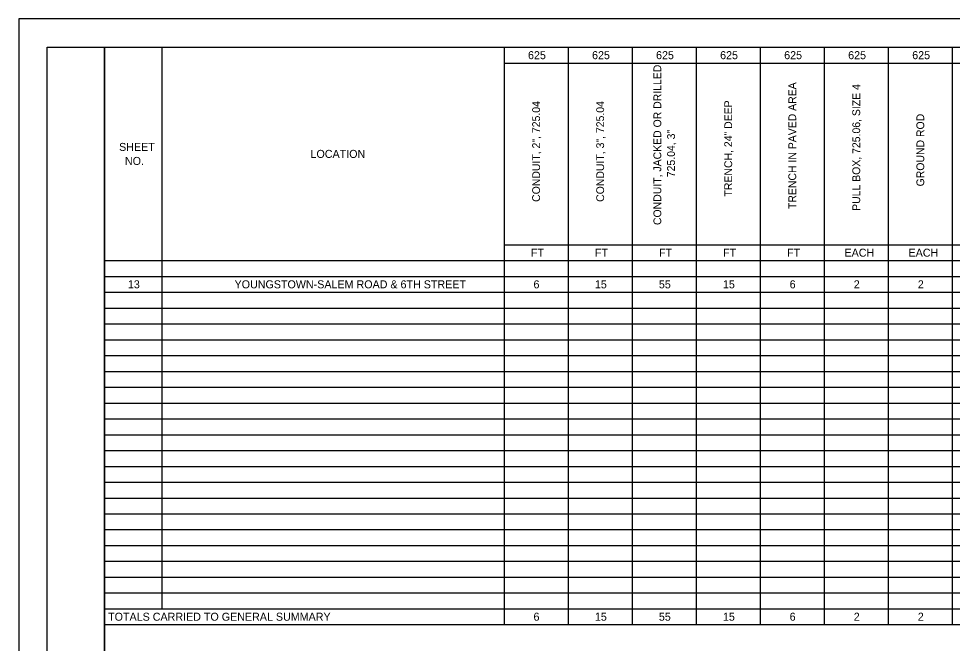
# Model space of a CAD drawing. Extents: x 0 to 34, y 0 to 22.
# Drawn here: x 0 to 16.33, y 11.08 to 22 of the extents above; entities that cross this region are included whole.
import ezdxf

# ---------------------------------------------------------------- set-up
doc = ezdxf.new("R2010")
doc.units = 0
for name, color, linetype in [('SH_Border', 7, 'Continuous'), ('SH_Cut_Line', 7, 'Continuous'), ('SH_Data', 7, 'Continuous')]:
    doc.layers.add(name, color=color, linetype=linetype)

msp = doc.modelspace()

# ---------------------------------------------------------------- linework, layer by layer
at = {"layer": 'SH_Border'}
for points in [[(0.5, 21.5), (1.5, 21.5), (1.5, 0.5), (0.5, 0.5)], [(1.5, 21.5), (33.5, 21.5), (33.5, 0.5), (1.5, 0.5)]]:
    msp.add_lwpolyline(points, close=True, dxfattribs=at)
at = {"layer": 'SH_Cut_Line'}
msp.add_lwpolyline([(0, 0), (34, 0), (34, 22), (0, 22)], close=True, dxfattribs=at)
at = {"layer": 'SH_Data'}
for p, q in [((1.5, 21.5), (6.249, 21.5)), ((1.5, 21.5), (1.5, 21.223)), ((2.504, 21.5), (2.504, 21.223)), ((6.249, 21.5), (7.716, 21.5)), ((7.716, 21.5), (14.086, 21.5)), ((8.488, 21.5), (8.488, 21.223)), ((9.608, 21.5), (9.608, 21.223)), ((10.727, 21.5), (10.727, 21.223)), ((11.847, 21.5), (11.847, 21.223)), ((12.966, 21.5), (12.966, 21.223)), ((14.086, 21.5), (15.206, 21.5)), ((14.086, 21.5), (14.086, 21.223)), ((15.206, 21.5), (16.325, 21.5)), ((15.206, 21.5), (15.206, 21.223)), ((16.325, 21.5), (23.043, 21.5)), ((16.325, 21.5), (16.325, 21.223)), ((1.5, 21.223), (1.5, 20.947)), ((2.504, 21.223), (2.504, 20.947)), ((8.488, 21.223), (14.086, 21.223)), ((8.488, 21.223), (8.488, 20.947)), ((9.608, 21.223), (9.608, 20.947)), ((10.727, 21.223), (10.727, 20.947)), ((11.847, 21.223), (11.847, 20.947)), ((12.966, 21.223), (12.966, 20.947)), ((14.086, 21.223), (15.206, 21.223)), ((14.086, 21.223), (14.086, 20.947)), ((15.206, 21.223), (16.325, 21.223)), ((15.206, 21.223), (15.206, 20.947)), ((16.325, 21.223), (23.043, 21.223)), ((16.325, 21.223), (16.325, 20.947)), ((1.5, 20.947), (1.5, 20.67)), ((2.504, 20.947), (2.504, 20.67)), ((8.488, 20.947), (8.488, 20.67)), ((9.608, 20.947), (9.608, 20.67)), ((10.727, 20.947), (10.727, 20.67)), ((11.847, 20.947), (11.847, 20.67)), ((12.966, 20.947), (12.966, 20.67)), ((14.086, 20.947), (14.086, 20.67)), ((15.206, 20.947), (15.206, 20.67)), ((16.325, 20.947), (16.325, 20.67)), ((1.5, 20.67), (1.5, 20.393)), ((2.504, 20.67), (2.504, 20.393)), ((8.488, 20.67), (8.488, 20.393)), ((9.608, 20.67), (9.608, 20.393)), ((10.727, 20.67), (10.727, 20.393)), ((11.847, 20.67), (11.847, 20.393)), ((12.966, 20.67), (12.966, 20.393)), ((14.086, 20.67), (14.086, 20.393)), ((15.206, 20.67), (15.206, 20.393)), ((16.325, 20.67), (16.325, 20.393)), ((1.5, 20.393), (1.5, 20.116)), ((2.504, 20.393), (2.504, 20.116)), ((8.488, 20.393), (8.488, 20.116)), ((9.608, 20.393), (9.608, 20.116)), ((10.727, 20.393), (10.727, 20.116)), ((11.847, 20.393), (11.847, 20.116)), ((12.966, 20.393), (12.966, 20.116)), ((14.086, 20.393), (14.086, 20.116)), ((15.206, 20.393), (15.206, 20.116)), ((16.325, 20.393), (16.325, 20.116)), ((1.5, 20.116), (1.5, 19.84)), ((2.504, 20.116), (2.504, 19.84)), ((8.488, 20.116), (8.488, 19.84)), ((9.608, 20.116), (9.608, 19.84)), ((10.727, 20.116), (10.727, 19.84)), ((11.847, 20.116), (11.847, 19.84)), ((12.966, 20.116), (12.966, 19.84)), ((14.086, 20.116), (14.086, 19.84)), ((15.206, 20.116), (15.206, 19.84)), ((16.325, 20.116), (16.325, 19.84)), ((1.5, 19.84), (1.5, 19.563)), ((2.504, 19.84), (2.504, 19.563)), ((8.488, 19.84), (8.488, 19.563)), ((9.608, 19.84), (9.608, 19.563)), ((10.727, 19.84), (10.727, 19.563)), ((11.847, 19.84), (11.847, 19.563)), ((12.966, 19.84), (12.966, 19.563)), ((14.086, 19.84), (14.086, 19.563)), ((15.206, 19.84), (15.206, 19.563)), ((16.325, 19.84), (16.325, 19.563)), ((1.5, 19.563), (1.5, 18.878)), ((2.504, 19.563), (2.504, 18.878)), ((8.488, 19.563), (8.488, 18.878)), ((9.608, 19.563), (9.608, 18.878)), ((10.727, 19.563), (10.727, 18.878)), ((11.847, 19.563), (11.847, 18.878)), ((12.966, 19.563), (12.966, 18.878)), ((14.086, 19.563), (14.086, 18.878)), ((15.206, 19.563), (15.206, 18.878)), ((16.325, 19.563), (16.325, 18.878)), ((1.5, 18.878), (1.5, 18.048)), ((2.504, 18.878), (2.504, 18.048)), ((8.488, 18.878), (8.488, 18.048)), ((9.608, 18.878), (9.608, 18.048)), ((10.727, 18.878), (10.727, 18.048)), ((11.847, 18.878), (11.847, 18.048)), ((12.966, 18.878), (12.966, 18.048)), ((14.086, 18.878), (14.086, 18.048)), ((15.206, 18.878), (15.206, 18.048)), ((16.325, 18.878), (16.325, 18.048)), ((1.5, 18.048), (1.5, 17.771)), ((2.504, 18.048), (2.504, 17.771)), ((8.488, 18.048), (14.086, 18.048)), ((8.488, 18.048), (8.488, 17.771)), ((9.608, 18.048), (9.608, 17.771)), ((10.727, 18.048), (10.727, 17.771)), ((11.847, 18.048), (11.847, 17.771)), ((12.966, 18.048), (12.966, 17.771)), ((14.086, 18.048), (15.206, 18.048)), ((14.086, 18.048), (14.086, 17.771)), ((15.206, 18.048), (16.325, 18.048)), ((15.206, 18.048), (15.206, 17.771)), ((16.325, 18.048), (23.043, 18.048)), ((16.325, 18.048), (16.325, 17.771)), ((1.5, 17.771), (6.249, 17.771)), ((1.5, 17.771), (1.5, 17.218)), ((2.504, 17.771), (2.504, 17.218)), ((6.249, 17.771), (7.716, 17.771)), ((7.716, 17.771), (14.086, 17.771)), ((8.488, 17.771), (8.488, 17.218)), ((9.608, 17.771), (9.608, 17.218)), ((10.727, 17.771), (10.727, 17.218)), ((11.847, 17.771), (11.847, 17.218)), ((12.966, 17.771), (12.966, 17.218)), ((14.086, 17.771), (15.206, 17.771)), ((14.086, 17.771), (14.086, 17.218)), ((15.206, 17.771), (16.325, 17.771)), ((15.206, 17.771), (15.206, 17.218)), ((16.325, 17.771), (23.043, 17.771)), ((16.325, 17.771), (16.325, 17.218)), ((1.5, 17.494), (6.249, 17.494)), ((6.249, 17.494), (7.716, 17.494)), ((7.716, 17.494), (14.086, 17.494)), ((14.086, 17.494), (15.206, 17.494)), ((15.206, 17.494), (16.325, 17.494)), ((16.325, 17.494), (23.043, 17.494)), ((1.5, 17.218), (6.249, 17.218)), ((1.5, 17.218), (1.5, 16.941)), ((2.504, 17.218), (2.504, 16.941)), ((6.249, 17.218), (7.716, 17.218)), ((7.716, 17.218), (14.086, 17.218)), ((8.488, 17.218), (8.488, 16.941)), ((9.608, 17.218), (9.608, 16.941)), ((10.727, 17.218), (10.727, 16.941)), ((11.847, 17.218), (11.847, 16.941)), ((12.966, 17.218), (12.966, 16.941)), ((14.086, 17.218), (15.206, 17.218)), ((14.086, 17.218), (14.086, 16.941)), ((15.206, 17.218), (16.325, 17.218)), ((15.206, 17.218), (15.206, 16.941)), ((16.325, 17.218), (23.043, 17.218)), ((16.325, 17.218), (16.325, 16.941)), ((1.5, 16.941), (6.249, 16.941)), ((1.5, 16.941), (1.5, 15.557)), ((2.504, 16.941), (2.504, 15.557)), ((6.249, 16.941), (7.716, 16.941)), ((7.716, 16.941), (14.086, 16.941)), ((8.488, 16.941), (8.488, 15.557)), ((9.608, 16.941), (9.608, 15.557)), ((10.727, 16.941), (10.727, 15.557)), ((11.847, 16.941), (11.847, 15.557)), ((12.966, 16.941), (12.966, 15.557)), ((14.086, 16.941), (15.206, 16.941)), ((14.086, 16.941), (14.086, 15.557)), ((15.206, 16.941), (16.325, 16.941)), ((15.206, 16.941), (15.206, 15.557)), ((16.325, 16.941), (23.043, 16.941)), ((16.325, 16.941), (16.325, 15.557)), ((1.5, 16.664), (6.249, 16.664)), ((6.249, 16.664), (7.716, 16.664)), ((7.716, 16.664), (14.086, 16.664)), ((14.086, 16.664), (15.206, 16.664)), ((15.206, 16.664), (16.325, 16.664)), ((16.325, 16.664), (23.043, 16.664)), ((1.5, 16.388), (6.249, 16.388)), ((6.249, 16.388), (7.716, 16.388)), ((7.716, 16.388), (14.086, 16.388)), ((14.086, 16.388), (15.206, 16.388)), ((15.206, 16.388), (16.325, 16.388)), ((16.325, 16.388), (23.043, 16.388)), ((1.5, 16.111), (6.249, 16.111)), ((6.249, 16.111), (7.716, 16.111)), ((7.716, 16.111), (14.086, 16.111)), ((14.086, 16.111), (15.206, 16.111)), ((15.206, 16.111), (16.325, 16.111)), ((16.325, 16.111), (23.043, 16.111)), ((1.5, 15.834), (6.249, 15.834)), ((6.249, 15.834), (7.716, 15.834)), ((7.716, 15.834), (14.086, 15.834)), ((14.086, 15.834), (15.206, 15.834)), ((15.206, 15.834), (16.325, 15.834)), ((16.325, 15.834), (23.043, 15.834)), ((1.5, 15.557), (6.249, 15.557)), ((1.5, 15.557), (1.5, 15.004)), ((2.504, 15.557), (2.504, 15.004)), ((6.249, 15.557), (7.716, 15.557)), ((7.716, 15.557), (14.086, 15.557)), ((8.488, 15.557), (8.488, 15.004)), ((9.608, 15.557), (9.608, 15.004)), ((10.727, 15.557), (10.727, 15.004)), ((11.847, 15.557), (11.847, 15.004)), ((12.966, 15.557), (12.966, 15.004)), ((14.086, 15.557), (15.206, 15.557)), ((14.086, 15.557), (14.086, 15.004)), ((15.206, 15.557), (16.325, 15.557)), ((15.206, 15.557), (15.206, 15.004)), ((16.325, 15.557), (23.043, 15.557)), ((16.325, 15.557), (16.325, 15.004)), ((1.5, 15.281), (6.249, 15.281)), ((6.249, 15.281), (7.716, 15.281)), ((7.716, 15.281), (14.086, 15.281)), ((14.086, 15.281), (15.206, 15.281)), ((15.206, 15.281), (16.325, 15.281)), ((16.325, 15.281), (23.043, 15.281)), ((1.5, 15.004), (6.249, 15.004)), ((1.5, 15.004), (1.5, 14.451)), ((2.504, 15.004), (2.504, 14.451)), ((6.249, 15.004), (7.716, 15.004)), ((7.716, 15.004), (14.086, 15.004)), ((8.488, 15.004), (8.488, 14.451)), ((9.608, 15.004), (9.608, 14.451)), ((10.727, 15.004), (10.727, 14.451)), ((11.847, 15.004), (11.847, 14.451)), ((12.966, 15.004), (12.966, 14.451)), ((14.086, 15.004), (15.206, 15.004)), ((14.086, 15.004), (14.086, 14.451)), ((15.206, 15.004), (16.325, 15.004)), ((15.206, 15.004), (15.206, 14.451)), ((16.325, 15.004), (23.043, 15.004)), ((16.325, 15.004), (16.325, 14.451)), ((1.5, 14.727), (6.249, 14.727)), ((6.249, 14.727), (7.716, 14.727)), ((7.716, 14.727), (14.086, 14.727)), ((14.086, 14.727), (15.206, 14.727)), ((15.206, 14.727), (16.325, 14.727)), ((16.325, 14.727), (23.043, 14.727)), ((1.5, 14.451), (6.249, 14.451)), ((1.5, 14.451), (1.5, 14.174)), ((2.504, 14.451), (2.504, 14.174)), ((6.249, 14.451), (7.716, 14.451)), ((7.716, 14.451), (14.086, 14.451)), ((8.488, 14.451), (8.488, 14.174)), ((9.608, 14.451), (9.608, 14.174)), ((10.727, 14.451), (10.727, 14.174)), ((11.847, 14.451), (11.847, 14.174)), ((12.966, 14.451), (12.966, 14.174)), ((14.086, 14.451), (15.206, 14.451)), ((14.086, 14.451), (14.086, 14.174)), ((15.206, 14.451), (16.325, 14.451)), ((15.206, 14.451), (15.206, 14.174)), ((16.325, 14.451), (23.043, 14.451)), ((16.325, 14.451), (16.325, 14.174)), ((1.5, 14.174), (6.249, 14.174)), ((1.5, 14.174), (1.5, 13.62)), ((2.504, 14.174), (2.504, 13.62)), ((6.249, 14.174), (7.716, 14.174)), ((7.716, 14.174), (14.086, 14.174)), ((8.488, 14.174), (8.488, 13.62)), ((9.608, 14.174), (9.608, 13.62)), ((10.727, 14.174), (10.727, 13.62)), ((11.847, 14.174), (11.847, 13.62)), ((12.966, 14.174), (12.966, 13.62)), ((14.086, 14.174), (15.206, 14.174)), ((14.086, 14.174), (14.086, 13.62)), ((15.206, 14.174), (16.325, 14.174)), ((15.206, 14.174), (15.206, 13.62)), ((16.325, 14.174), (23.043, 14.174)), ((16.325, 14.174), (16.325, 13.62)), ((1.5, 13.897), (6.249, 13.897)), ((6.249, 13.897), (7.716, 13.897)), ((7.716, 13.897), (14.086, 13.897)), ((14.086, 13.897), (15.206, 13.897)), ((15.206, 13.897), (16.325, 13.897)), ((16.325, 13.897), (23.043, 13.897)), ((1.5, 13.62), (6.249, 13.62)), ((1.5, 13.62), (1.5, 13.344)), ((2.504, 13.62), (2.504, 13.344)), ((6.249, 13.62), (7.716, 13.62)), ((7.716, 13.62), (14.086, 13.62)), ((8.488, 13.62), (8.488, 13.344)), ((9.608, 13.62), (9.608, 13.344)), ((10.727, 13.62), (10.727, 13.344)), ((11.847, 13.62), (11.847, 13.344)), ((12.966, 13.62), (12.966, 13.344)), ((14.086, 13.62), (15.206, 13.62)), ((14.086, 13.62), (14.086, 13.344)), ((15.206, 13.62), (16.325, 13.62)), ((15.206, 13.62), (15.206, 13.344)), ((16.325, 13.62), (23.043, 13.62)), ((16.325, 13.62), (16.325, 13.344)), ((1.5, 13.344), (6.249, 13.344)), ((1.5, 13.344), (1.5, 12.514)), ((2.504, 13.344), (2.504, 12.514)), ((6.249, 13.344), (7.716, 13.344)), ((7.716, 13.344), (14.086, 13.344)), ((8.488, 13.344), (8.488, 12.514)), ((9.608, 13.344), (9.608, 12.514)), ((10.727, 13.344), (10.727, 12.514)), ((11.847, 13.344), (11.847, 12.514)), ((12.966, 13.344), (12.966, 12.514)), ((14.086, 13.344), (15.206, 13.344)), ((14.086, 13.344), (14.086, 12.514)), ((15.206, 13.344), (16.325, 13.344)), ((15.206, 13.344), (15.206, 12.514)), ((16.325, 13.344), (23.043, 13.344)), ((16.325, 13.344), (16.325, 12.514)), ((1.5, 13.067), (6.249, 13.067)), ((6.249, 13.067), (7.716, 13.067)), ((7.716, 13.067), (14.086, 13.067)), ((14.086, 13.067), (15.206, 13.067)), ((15.206, 13.067), (16.325, 13.067)), ((16.325, 13.067), (23.043, 13.067)), ((1.5, 12.79), (6.249, 12.79)), ((6.249, 12.79), (7.716, 12.79)), ((7.716, 12.79), (14.086, 12.79)), ((14.086, 12.79), (15.206, 12.79)), ((15.206, 12.79), (16.325, 12.79)), ((16.325, 12.79), (23.043, 12.79)), ((1.5, 12.514), (6.249, 12.514)), ((1.5, 12.514), (1.5, 11.96)), ((2.504, 12.514), (2.504, 11.96)), ((6.249, 12.514), (7.716, 12.514)), ((7.716, 12.514), (14.086, 12.514)), ((8.488, 12.514), (8.488, 11.96)), ((9.608, 12.514), (9.608, 11.96)), ((10.727, 12.514), (10.727, 11.96)), ((11.847, 12.514), (11.847, 11.96)), ((12.966, 12.514), (12.966, 11.96)), ((14.086, 12.514), (15.206, 12.514)), ((14.086, 12.514), (14.086, 11.96)), ((15.206, 12.514), (16.325, 12.514)), ((15.206, 12.514), (15.206, 11.96)), ((16.325, 12.514), (23.043, 12.514)), ((16.325, 12.514), (16.325, 11.96)), ((1.5, 12.237), (6.249, 12.237)), ((6.249, 12.237), (7.716, 12.237)), ((7.716, 12.237), (14.086, 12.237)), ((14.086, 12.237), (15.206, 12.237)), ((15.206, 12.237), (16.325, 12.237)), ((16.325, 12.237), (23.043, 12.237)), ((1.5, 11.96), (6.249, 11.96)), ((1.5, 11.96), (1.5, 11.407)), ((2.504, 11.96), (2.504, 11.684)), ((6.249, 11.96), (7.716, 11.96)), ((7.716, 11.96), (14.086, 11.96)), ((8.488, 11.96), (8.488, 11.407)), ((9.608, 11.96), (9.608, 11.407)), ((10.727, 11.96), (10.727, 11.407)), ((11.847, 11.96), (11.847, 11.407)), ((12.966, 11.96), (12.966, 11.407)), ((14.086, 11.96), (15.206, 11.96)), ((14.086, 11.96), (14.086, 11.407)), ((15.206, 11.96), (16.325, 11.96)), ((15.206, 11.96), (15.206, 11.407)), ((16.325, 11.96), (23.043, 11.96)), ((16.325, 11.96), (16.325, 11.407)), ((1.5, 11.684), (6.249, 11.684)), ((6.249, 11.684), (7.716, 11.684)), ((7.716, 11.684), (14.086, 11.684)), ((14.086, 11.684), (15.206, 11.684)), ((15.206, 11.684), (16.325, 11.684)), ((16.325, 11.684), (23.043, 11.684)), ((1.5, 11.407), (6.249, 11.407)), ((6.249, 11.407), (7.716, 11.407)), ((7.716, 11.407), (14.086, 11.407)), ((14.086, 11.407), (15.206, 11.407)), ((15.206, 11.407), (16.325, 11.407)), ((16.325, 11.407), (23.043, 11.407))]:
    msp.add_line(p, q, dxfattribs=at)

# ---------------------------------------------------------------- texts
for s, p in [('625', (8.906, 21.292)), ('625', (10.026, 21.292)), ('625', (11.145, 21.292)), ('625', (12.265, 21.292)), ('625', (13.385, 21.292)), ('625', (14.504, 21.292)), ('625', (15.624, 21.292)), ('SHEET', (1.756, 19.688)), ('LOCATION', (5.103, 19.566)), ('NO.', (1.858, 19.443)), ('FT', (8.957, 17.839)), ('FT', (10.076, 17.839)), ('FT', (11.196, 17.839)), ('FT', (12.316, 17.839)), ('FT', (13.435, 17.839)), ('EACH', (14.44, 17.839)), ('EACH', (15.56, 17.839)), ('13', (1.91, 17.286)), ('YOUNGSTOWN-SALEM ROAD & 6TH STREET', (3.775, 17.286)), ('6', (9.002, 17.286)), ('15', (10.075, 17.286)), ('55', (11.194, 17.286)), ('15', (12.314, 17.286)), ('6', (13.481, 17.286)), ('2', (14.602, 17.286)), ('2', (15.722, 17.286)), ('TOTALS CARRIED TO GENERAL SUMMARY', (1.564, 11.475)), ('6', (9.002, 11.475)), ('15', (10.075, 11.475)), ('55', (11.194, 11.475)), ('15', (12.314, 11.475)), ('6', (13.481, 11.475)), ('2', (14.602, 11.475)), ('2', (15.722, 11.475))]:
    msp.add_text(s, height=0.14, dxfattribs=at).set_placement(p)
for s, height, p in [('CONDUIT, JACKED OR DRILLED, ', 0.13674, (11.236, 18.392)), ('TRENCH IN PAVED AREA', 0.13674, (13.595, 18.672)), ('PULL BOX, 725.06, SIZE 4', 0.13674, (14.714, 18.64)), ('CONDUIT, 2", 725.04', 0.13674, (9.116, 18.797)), ('CONDUIT, 3", 725.04', 0.13674, (10.236, 18.797)), ('TRENCH, 24" DEEP', 0.13674, (12.475, 18.891)), ('GROUND ROD', 0.1367, (15.834, 19.068)), ('725.04, 3"', 0.1367, (11.475, 19.229))]:
    msp.add_text(s, height=height, rotation=90, dxfattribs=at).set_placement(p)

doc.saveas('drawing.dxf')
